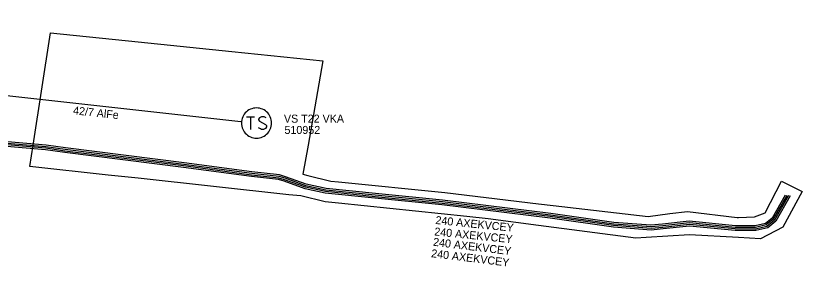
# Model space of a CAD drawing. Extents: x -536397 to -535454, y -1201642 to -1200953.
# Drawn here: x -536177.8 to -536079.5, y -1201327.6 to -1201296.4 of the extents above; entities that cross this region are included whole.
import ezdxf

# ---------------------------------------------------------------- set-up
doc = ezdxf.new("R2010")
doc.units = 0
for name, color, linetype in [('KN_HRAN_K_Ú', 7, 'Continuous'), ('KN_HRAN_KRAJSKÁ', 7, 'Continuous'), ('KN_PARC_Č', 7, 'Continuous'), ('PK_HRAN_SPORNÁ', 7, 'Continuous'), ('PROJEKT', 7, 'Continuous'), ('SDEL_EON_POPIS', 7, 'Continuous'), ('SR', 7, 'Continuous'), ('ZRUŠENO', 7, 'Continuous')]:
    doc.layers.add(name, color=color, linetype=linetype)

# ---------------------------------------------------------------- blocks, each defined once
blk = doc.blocks.new('VN610')
at = {"layer": 'ZRUŠENO'}
for points in [[(1.883, -0.001), (1.872, 0.196), (1.841, 0.392), (1.79, 0.583), (1.718, 0.768), (1.629, 0.943), (1.521, 1.109), (1.397, 1.263), (1.257, 1.403), (1.103, 1.527), (0.937, 1.635), (0.761, 1.725), (0.577, 1.796), (0.385, 1.847), (0.19, 1.878), (-0.007, 1.889), (-0.205, 1.878), (-0.401, 1.847), (-0.591, 1.796), (-0.777, 1.725), (-0.952, 1.635), (-1.118, 1.527), (-1.272, 1.403), (-1.412, 1.263), (-1.536, 1.109), (-1.644, 0.943), (-1.734, 0.768), (-1.805, 0.583), (-1.856, 0.392), (-1.887, 0.196), (-1.898, -0.001), (-1.887, -0.199), (-1.856, -0.395), (-1.805, -0.585), (-1.734, -0.77), (-1.644, -0.946), (-1.536, -1.112), (-1.411, -1.266), (-1.272, -1.405), (-1.118, -1.53), (-0.952, -1.638), (-0.776, -1.728), (-0.591, -1.799), (-0.401, -1.85), (-0.205, -1.881), (-0.007, -1.892), (0.19, -1.881), (0.385, -1.85), (0.577, -1.799), (0.761, -1.728), (0.937, -1.638), (1.103, -1.53), (1.257, -1.405), (1.397, -1.266), (1.521, -1.112), (1.629, -0.946), (1.718, -0.77), (1.79, -0.585), (1.841, -0.395), (1.872, -0.199), (1.883, -0.001)], [(-1.269, 0.782), (-0.261, 0.782)], [(-0.765, 0.782), (-0.765, -0.792)], [(1.188, 0.656), (0.936, 0.782), (0.621, 0.782), (0.369, 0.656), (0.243, 0.468), (0.243, 0.404), (0.369, 0.216), (1.125, -0.162), (1.251, -0.32), (1.251, -0.478), (1.125, -0.666), (0.873, -0.792), (0.621, -0.792), (0.495, -0.73), (0.243, -0.604)]]:
    blk.add_lwpolyline(points, dxfattribs=at)

msp = doc.modelspace()

# ---------------------------------------------------------------- linework, layer by layer
at = {"layer": 'PK_HRAN_SPORNÁ'}
msp.add_lwpolyline([(-536138.46, -1201317.01), (-536137.5, -1201317.1), (-536124.22, -1201318.41), (-536119.04, -1201319.04), (-536112.5, -1201319.83), (-536110.67, -1201320.05), (-536098.79, -1201321.42), (-536096.07, -1201321.07), (-536093.87, -1201320.79), (-536087.69, -1201321.55), (-536087.5, -1201321.54), (-536085.51, -1201321.45), (-536084.19, -1201320.96), (-536082.15, -1201317.03), (-536079.54, -1201318.31), (-536081.95, -1201322.74), (-536084.75, -1201324.2), (-536087.5, -1201324.04), (-536093.62, -1201323.7), (-536099.05, -1201324.05), (-536100.32, -1201324.13), (-536112.5, -1201322.53), (-536118.8, -1201321.71), (-536121.43, -1201321.43), (-536137.5, -1201319.75), (-536139.14, -1201319.58), (-536142.2, -1201318.86), (-536143.7, -1201318.7), (-536162.5, -1201316.65), (-536166.25, -1201316.25), (-536176.07, -1201315.18), (-536175.65, -1201312.5), (-536173.46, -1201298.49), (-536162.5, -1201299.62), (-536150.83, -1201300.83), (-536139.43, -1201302.01), (-536141.28, -1201312.5), (-536141.93, -1201316.15), (-536141.3, -1201316.3)], close=True, dxfattribs=at)
at = {"layer": 'PROJEKT'}
for points in [[(-536081.476, -1201318.79), (-536083.16, -1201321.76), (-536084.04, -1201322.47), (-536085.39, -1201322.79), (-536087.91, -1201322.78), (-536093.65, -1201322.22), (-536096.97, -1201322.58), (-536098.44, -1201322.72), (-536103.09, -1201322.37), (-536111, -1201321.24), (-536124.51, -1201319.59), (-536132.89, -1201318.75), (-536139.07, -1201318.12), (-536141.56, -1201317.59), (-536144.16, -1201316.65), (-536144.9, -1201316.43), (-536148.32, -1201316.05), (-536156.807, -1201314.921), (-536171.637, -1201313.051), (-536174.039, -1201312.711), (-536181.328, -1201312.091)], [(-536081.692, -1201318.766), (-536083.315, -1201321.628), (-536084.13, -1201322.286), (-536085.413, -1201322.59), (-536087.9, -1201322.58), (-536093.651, -1201322.019), (-536096.99, -1201322.381), (-536098.442, -1201322.519), (-536103.068, -1201322.171), (-536110.974, -1201321.042), (-536124.488, -1201319.391), (-536132.87, -1201318.551), (-536139.039, -1201317.922), (-536141.505, -1201317.397), (-536144.097, -1201316.46), (-536144.86, -1201316.233), (-536148.298, -1201315.851), (-536156.782, -1201314.722), (-536171.61, -1201312.853), (-536174.016, -1201312.512), (-536181.304, -1201311.892)], [(-536081.044, -1201318.84), (-536082.85, -1201322.024), (-536083.859, -1201322.838), (-536085.344, -1201323.19), (-536087.93, -1201323.18), (-536093.648, -1201322.622), (-536096.929, -1201322.978), (-536098.436, -1201323.121), (-536103.133, -1201322.768), (-536111.053, -1201321.637), (-536124.554, -1201319.988), (-536132.93, -1201319.148), (-536139.132, -1201318.516), (-536141.67, -1201317.976), (-536144.285, -1201317.03), (-536144.98, -1201316.824), (-536148.364, -1201316.448), (-536156.858, -1201315.318), (-536171.69, -1201313.447), (-536174.084, -1201313.108), (-536181.376, -1201312.488)], [(-536081.26, -1201318.815), (-536083.005, -1201321.892), (-536083.95, -1201322.654), (-536085.367, -1201322.99), (-536087.92, -1201322.98), (-536093.649, -1201322.421), (-536096.95, -1201322.779), (-536098.438, -1201322.921), (-536103.112, -1201322.569), (-536111.026, -1201321.438), (-536124.532, -1201319.789), (-536132.91, -1201318.949), (-536139.101, -1201318.318), (-536141.615, -1201317.783), (-536144.223, -1201316.84), (-536144.94, -1201316.627), (-536148.342, -1201316.249), (-536156.833, -1201315.119), (-536171.663, -1201313.249), (-536174.061, -1201312.909), (-536181.352, -1201312.289)]]:
    msp.add_lwpolyline(points, dxfattribs=at)
at = {"layer": 'SDEL_EON_POPIS'}
msp.add_lwpolyline([(-536199.36, -1201296.36), (-536187.58, -1201305.35), (-536149.67, -1201309.545)], dxfattribs=at)

# ---------------------------------------------------------------- block references
at = {"layer": 'KN_HRAN_KRAJSKÁ', "rotation": 0.005252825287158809}
msp.add_blockref('VN610', (-536147.722, -1201309.758), dxfattribs=at)

# ---------------------------------------------------------------- texts
at = {"layer": 'KN_HRAN_K_Ú'}
msp.add_text('510952', height=1, dxfattribs=at).set_placement((-536144.235, -1201311.117))
at = {"layer": 'KN_PARC_Č'}
msp.add_text('VS T22 VKA', height=1, dxfattribs=at).set_placement((-536144.303, -1201309.707))
at = {"layer": 'SR'}
msp.add_text('42/7 AlFe', height=1, rotation=353.82, dxfattribs=at).set_placement((-536170.687, -1201308.655))
at = {"layer": 'ZRUŠENO'}
for rotation, p in [(354.277, (-536125.41, -1201322.352)), (354.276, (-536125.553, -1201323.781)), (353.039, (-536125.707, -1201325.066)), (353.036, (-536125.945, -1201326.495))]:
    msp.add_text('240 AXEKVCEY', height=1, rotation=rotation, dxfattribs=at).set_placement(p)

doc.saveas('drawing.dxf')
